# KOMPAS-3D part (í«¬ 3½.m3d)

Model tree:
1. Эскиз:1
2. Операция выдавливания:1
     Расстояние 1 = 2
3. Эскиз:2
4. Операция выдавливания:2
     Расстояние 1 = 5
5. Эскиз:3
6. Операция выдавливания:3
     Расстояние 1 = 2
7. Эскиз:4
8. Операция выдавливания:4
     Расстояние 1 = 60
9. Эскиз:5
10. Операция выдавливания:5
     Расстояние 1 = 2
11. Эскиз:6
12. Операция выдавливания:6
     Расстояние 1 = 4.5
13. Эскиз:7
14. Операция выдавливания:7
     Расстояние 1 = 2
15. Скругление:1
     Радиус = 1
16. Скругление:2
     Радиус = 1
17. Эскиз:8
18. Вырезать элемент выдавливания:1
     Расстояние 1 = 10; Угол 1 = 35
19. Эскиз:9
20. Вырезать элемент выдавливания:2
     Расстояние 1 = 10; Угол 1 = 35
21. Эскиз:10
22. Вырезать элемент выдавливания:3
     Расстояние 2 = 22; Расстояние 1 = 22; Угол 1 = 35
23. Эскиз:11
24. Вырезать элемент выдавливания:4
     Расстояние 2 = 2; Расстояние 1 = 2
25. Эскиз:12
26. Вырезать элемент выдавливания:5
     Расстояние 2 = 2; Расстояние 1 = 2; Угол 1 = 35
27. Эскиз:13
28. Вырезать элемент выдавливания:6
     Расстояние 2 = 2; Расстояние 1 = 122
29. Эскиз:15
30. Операция выдавливания:9
     Расстояние 1 = 10; Расстояние 2 = 0.5
